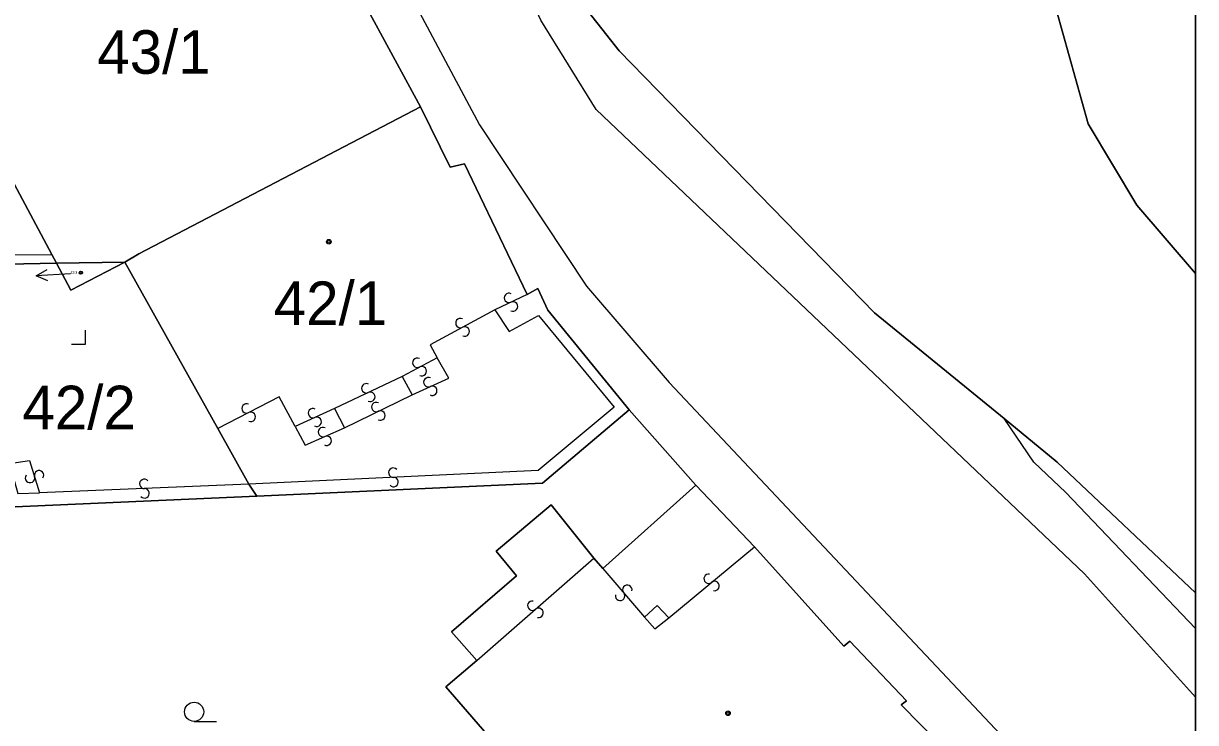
# Model space of a CAD drawing. Extents: x -600309 to -598967, y -1161267 to -1160292.
# Drawn here: x -599012.86 to -598967.11, y -1160889.91 to -1160862.6 of the extents above; entities that cross this region are included whole.
import ezdxf

# ---------------------------------------------------------------- set-up
doc = ezdxf.new("R2010")
doc.units = 0
for name, color, linetype in [('Level 1', 7, 'Continuous'), ('Level 13', 7, 'Continuous'), ('Level 3', 7, 'Continuous'), ('Level 4', 7, 'Continuous'), ('Level 5', 7, 'Continuous'), ('Level 57', 7, 'Continuous'), ('Level 60', 7, 'Continuous'), ('Vrstva 60', 7, 'Continuous'), ('Vrstva 63', 7, 'Continuous')]:
    doc.layers.add(name, color=color, linetype=linetype)

msp = doc.modelspace()

# ---------------------------------------------------------------- linework, layer by layer
at = {"layer": 'Level 1'}
for points in [[(-598967.108, -1160884.839), (-598972.51, -1160879.73), (-598974.58, -1160878.03), (-598979.64, -1160873.91), (-598989.61, -1160863.67), (-598991.16, -1160861.71), (-599008.15, -1160829.7), (-599020.75, -1160807.03), (-599038.86, -1160772.13)], [(-598974.58, -1160878.03), (-598979.64, -1160873.91), (-598989.61, -1160863.67), (-598991.16, -1160861.71), (-599008.15, -1160829.7)], [(-598967.108, -1160872.375), (-598969.4, -1160869.7), (-598971.3, -1160866.53), (-598974.52, -1160855), (-598967.76, -1160834.36)], [(-598997.36, -1160865.86), (-599003.95, -1160853.72)], [(-599011.75, -1160871.63), (-599017.49, -1160860.88), (-599017.29, -1160860.77)], [(-599008.91, -1160871.92), (-599008.36, -1160871.6), (-598997.36, -1160865.86)], [(-598993.2, -1160873.19), (-598995.65, -1160868.08), (-598996.21, -1160868.21), (-598997.36, -1160865.86)], [(-599011.57, -1160871.97), (-599011.75, -1160871.63)], [(-599008.91, -1160871.92), (-599011.57, -1160871.97)], [(-599008.91, -1160871.92), (-599011.01, -1160873.02), (-599011.57, -1160871.97)], [(-599005.27, -1160878.42), (-599008.91, -1160871.92)], [(-599015.41, -1160872.04), (-599011.57, -1160871.97)], [(-598989.22, -1160877.69), (-598992.39, -1160873.8), (-598992.78, -1160872.96), (-598993.2, -1160873.19)], [(-598989.22, -1160877.69), (-598992.6, -1160880.56), (-599003.75, -1160881.07)], [(-598986.62, -1160880.63), (-598989.22, -1160877.69)], [(-598974.58, -1160878.03), (-598972.51, -1160879.73), (-598967.108, -1160884.839)], [(-599004.06, -1160880.6), (-599005.27, -1160878.42)], [(-599003.75, -1160881.07), (-599004.06, -1160880.6)], [(-598990.24, -1160883.89), (-598986.62, -1160880.63)], [(-598984.33, -1160883.04), (-598986.62, -1160880.63)], [(-599013.49, -1160881.49), (-599003.75, -1160881.07)], [(-598995.16, -1160887.48), (-598996.15, -1160886.36), (-598993.62, -1160884.17), (-598994.41, -1160883.21), (-598992.26, -1160881.4), (-598990.6, -1160883.49)], [(-598974.12, -1160893.77), (-598978.6, -1160889.21), (-598978.39, -1160889.06), (-598980.6, -1160886.72), (-598980.84, -1160886.92), (-598984.33, -1160883.04)], [(-598990.6, -1160883.49), (-598990.24, -1160883.89)], [(-598994.27, -1160890.94), (-598996.37, -1160888.51), (-598995.16, -1160887.48)]]:
    msp.add_lwpolyline(points, dxfattribs=at)
at = {"layer": 'Level 13'}
for centre, start, end in [((-598993.908, -1160873.323), 62.6216, 295.2116), ((-598993.752, -1160873.657), 242.8361, 114.9341), ((-598995.806, -1160874.307), 65.4185, 298.0085), ((-598995.634, -1160874.633), 245.633, 117.731), ((-598997.486, -1160875.857), 65.2091, 297.7991), ((-598997.315, -1160876.184), 245.4235, 117.5215), ((-598997.056, -1160876.612), 62.1479, 294.2459), ((-598999.478, -1160876.853), 62.4951, 295.0851), ((-598996.904, -1160876.947), 241.9334, 114.5234), ((-598999.323, -1160877.187), 242.7096, 114.8076), ((-598999.089, -1160877.583), 63.2391, 295.3371), ((-599004.154, -1160877.636), 64.3906, 296.9806), ((-599003.987, -1160877.965), 244.6051, 116.7031), ((-599001.565, -1160877.822), 61.6022, 294.1922), ((-598998.93, -1160877.916), 243.0246, 115.6146), ((-599001.415, -1160878.159), 241.8167, 113.9147), ((-599001.173, -1160878.561), 61.197, 293.295), ((-599001.026, -1160878.899), 240.9825, 113.5725), ((-599012.253, -1160880.247), 324.5713, 196.6693), ((-598998.428, -1160880.146), 39.8966, 272.4866), ((-599012.606, -1160880.354), 144.3568, 16.9468), ((-599008.147, -1160880.586), 39.4713, 272.0613), ((-598998.413, -1160880.514), 220.1111, 92.2091), ((-599008.134, -1160880.954), 219.6857, 91.7837), ((-598986.117, -1160884.287), 77.1445, 309.2425), ((-598989.289, -1160884.722), 347.8247, 219.9227), ((-598985.883, -1160884.572), 256.9301, 129.5201), ((-598993, -1160885.34), 78.5587, 310.6567), ((-598989.571, -1160884.959), 167.6102, 40.2002), ((-598992.759, -1160885.619), 258.3442, 130.9342)]:
    msp.add_arc(centre, 0.184, start, end, dxfattribs=at)
at = {"layer": 'Level 3'}
for points in [[(-599044.45, -1160775.03), (-599042.71, -1160778.18), (-599027.74, -1160805.48), (-599010.55, -1160837.55), (-598995.06, -1160866.56), (-598990.88, -1160872.86), (-598987.65, -1160876.63), (-598967.63, -1160897.91), (-598967.108, -1160898.408)], [(-598967.108, -1160888.916), (-598971.44, -1160884.1), (-598990.51, -1160865.96), (-598992.66, -1160862.48), (-598993.99, -1160859.59), (-598995.19, -1160857.35), (-599007.23, -1160835.25), (-599008.15, -1160829.7)], [(-599026.6, -1160871.76), (-599011.75, -1160871.63)], [(-598993.2, -1160873.19), (-598994.46, -1160873.79)], [(-598994.46, -1160873.79), (-598993.9, -1160874.64), (-598992.76, -1160874.01), (-598989.8, -1160877.59), (-598992.77, -1160880.06), (-599004.06, -1160880.6)], [(-598994.46, -1160873.79), (-598996.99, -1160875.15), (-598996.71, -1160875.66)], [(-598996.71, -1160875.66), (-598998.08, -1160876.39)], [(-598997.69, -1160877.11), (-598996.26, -1160876.45), (-598996.71, -1160875.66)], [(-598998.08, -1160876.39), (-599000.72, -1160877.64)], [(-598998.08, -1160876.39), (-598997.69, -1160877.11)], [(-599002.26, -1160878.34), (-599002.88, -1160877.19), (-599005.27, -1160878.42)], [(-599000.33, -1160878.39), (-598997.69, -1160877.11)], [(-599000.72, -1160877.64), (-599002.26, -1160878.34)], [(-599000.72, -1160877.64), (-599000.33, -1160878.39)], [(-599002.26, -1160878.34), (-599001.87, -1160879.07), (-599000.33, -1160878.39)], [(-598967.108, -1160886.238), (-598972.17, -1160880.92), (-598973.42, -1160879.73), (-598974.58, -1160878.03)], [(-599013.41, -1160879.79), (-599012.62, -1160879.67), (-599012.23, -1160880.93)], [(-599013.41, -1160879.79), (-599013.08, -1160880.96), (-599012.23, -1160880.93)], [(-599004.06, -1160880.6), (-599012.23, -1160880.93)], [(-598987.67, -1160885.82), (-598984.33, -1160883.04)], [(-598995.16, -1160887.48), (-598990.6, -1160883.49)], [(-598990.24, -1160883.89), (-598988.62, -1160885.79)], [(-598988.62, -1160885.79), (-598988.13, -1160885.33), (-598987.67, -1160885.82)], [(-598988.62, -1160885.79), (-598988.21, -1160886.25), (-598987.67, -1160885.82)]]:
    msp.add_lwpolyline(points, dxfattribs=at)
at = {"layer": 'Level 5'}
msp.add_line((-599006.2, -1160889.86), (-599005.325, -1160889.86), dxfattribs=at)
msp.add_lwpolyline([(-599010.99, -1160875.13), (-599010.44, -1160875.13), (-599010.44, -1160874.58)], dxfattribs=at)
for centre, radius in [((-599000.94, -1160871.13), 0.09), ((-599000.94, -1160871.13), 0.0521), ((-599010.62, -1160872.34), 0.0612), ((-599010.62, -1160872.34), 0.0354), ((-599006.2, -1160889.485), 0.375), ((-598985.36, -1160889.54), 0.09), ((-598985.36, -1160889.54), 0.0521)]:
    msp.add_circle(centre, radius, dxfattribs=at)
at = {"layer": 'Level 57'}
msp.add_line((-599011.03, -1160872.38), (-599012.37, -1160872.46), dxfattribs=at)
msp.add_lwpolyline([(-599011.91, -1160872.657), (-599012.37, -1160872.46), (-599011.937, -1160872.21)], dxfattribs=at)
at = {"layer": 'Level 60'}
for points in [[(-599003.95, -1160853.72), (-598997.36, -1160865.86), (-599008.36, -1160871.6), (-599008.91, -1160871.92), (-599011.57, -1160871.97), (-599011.75, -1160871.63), (-599017.49, -1160860.88), (-599017.29, -1160860.77)], [(-599015.8, -1160872.07), (-599026.53, -1160872.12), (-599026.6, -1160871.76), (-599030.78, -1160860.65), (-599021.56, -1160860.71), (-599017.29, -1160860.77), (-599017.49, -1160860.88), (-599011.75, -1160871.63), (-599011.57, -1160871.97), (-599015.41, -1160872.04)], [(-598992.39, -1160873.8), (-598989.22, -1160877.69), (-598992.6, -1160880.56), (-599003.75, -1160881.07), (-599004.06, -1160880.6), (-599005.27, -1160878.42), (-599008.91, -1160871.92), (-599008.36, -1160871.6), (-598997.36, -1160865.86), (-598996.21, -1160868.21), (-598995.65, -1160868.08), (-598993.2, -1160873.19), (-598992.78, -1160872.96)], [(-599003.75, -1160881.07), (-599013.49, -1160881.49), (-599013.61, -1160880.98), (-599015.8, -1160872.07), (-599015.41, -1160872.04), (-599011.57, -1160871.97), (-599011.01, -1160873.02), (-599008.91, -1160871.92), (-599005.27, -1160878.42), (-599004.06, -1160880.6)], [(-599011.57, -1160871.97), (-599008.91, -1160871.92), (-599011.01, -1160873.02)], [(-598978.6, -1160889.21), (-598974.12, -1160893.77), (-598982.46, -1160901.47), (-598982.92, -1160901.03), (-598987.26, -1160896.5), (-598989.27, -1160898.4), (-598993.03, -1160894.11), (-598995.16, -1160895.73), (-598997.15, -1160893.06), (-598994.27, -1160890.94), (-598996.37, -1160888.51), (-598995.16, -1160887.48), (-598996.15, -1160886.36), (-598993.62, -1160884.17), (-598994.41, -1160883.21), (-598992.26, -1160881.4), (-598990.6, -1160883.49), (-598990.24, -1160883.89), (-598986.62, -1160880.63), (-598984.33, -1160883.04), (-598980.84, -1160886.92), (-598980.6, -1160886.72), (-598978.39, -1160889.06)]]:
    msp.add_lwpolyline(points, close=True, dxfattribs=at)
msp.add_lwpolyline([(-599013.49, -1160881.49), (-599003.75, -1160881.07), (-598992.6, -1160880.56), (-598989.22, -1160877.69), (-598986.62, -1160880.63), (-598990.24, -1160883.89), (-598990.6, -1160883.49), (-598992.26, -1160881.4), (-598994.41, -1160883.21), (-598993.62, -1160884.17), (-598996.15, -1160886.36), (-598995.16, -1160887.48), (-598996.37, -1160888.51), (-598994.27, -1160890.94)], dxfattribs=at)
at = {"layer": 'Vrstva 60'}
for points in [[(-599038.86, -1160772.13), (-599020.75, -1160807.03), (-599008.15, -1160829.7), (-598991.16, -1160861.71), (-598989.61, -1160863.67), (-598979.64, -1160873.91), (-598974.58, -1160878.03), (-598972.51, -1160879.73), (-598967.108, -1160884.839), (-598967.108, -1160872.375), (-598969.4, -1160869.7), (-598971.3, -1160866.53), (-598974.52, -1160855), (-598967.76, -1160834.36), (-598967.108, -1160834.936), (-598967.108, -1160799.774), (-598974.62, -1160792.64), (-598983.72, -1160784.03), (-598987.65, -1160780.53)], [(-599003.95, -1160853.72), (-598997.36, -1160865.86), (-598996.21, -1160868.21), (-598995.65, -1160868.08), (-598993.2, -1160873.19), (-598992.78, -1160872.96), (-598992.39, -1160873.8), (-598989.22, -1160877.69), (-598986.62, -1160880.63), (-598984.33, -1160883.04), (-598980.84, -1160886.92), (-598980.6, -1160886.72), (-598978.39, -1160889.06), (-598978.6, -1160889.21), (-598974.12, -1160893.77)], [(-598967.108, -1160900.384), (-598967.108, -1160884.839), (-598972.51, -1160879.73), (-598974.58, -1160878.03), (-598979.64, -1160873.91), (-598989.61, -1160863.67), (-598991.16, -1160861.71)]]:
    msp.add_lwpolyline(points, dxfattribs=at)
msp.add_lwpolyline([(-598967.108, -1160872.375), (-598967.108, -1160834.936), (-598967.76, -1160834.36), (-598974.52, -1160855), (-598971.3, -1160866.53), (-598969.4, -1160869.7)], close=True, dxfattribs=at)
at = {"layer": 'Vrstva 63'}
msp.add_lwpolyline([(-600308.541, -1160292.347), (-598967.108, -1160292.347), (-598967.108, -1161267.031), (-600308.541, -1161267.031)], close=True, dxfattribs=at)

# ---------------------------------------------------------------- texts
at = {"layer": 'Level 4'}
for s, p in [('43/1', (-599009.98, -1160864.57)), ('42/1', (-599003.09, -1160874.38)), ('42/2', (-599012.9, -1160878.45))]:
    msp.add_text(s, height=1.7, dxfattribs=at).set_placement(p)
msp.add_text('42/3', height=0.1, rotation=0.9, dxfattribs=at).set_placement((-599011.03, -1160872.38))

doc.saveas('drawing.dxf')
